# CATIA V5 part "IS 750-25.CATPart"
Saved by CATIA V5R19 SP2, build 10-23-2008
Part number: IS 750-25
Bounding box of the stored display mesh (mm): x -24.865 to 24.865, y -24.997 to 24.997, z 0 to 145
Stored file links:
  C:\Users\Bora\Desktop\3D Katı model\IS serisi\IS 750\IS 750-25.CATPart
  C:\Program Files\Dassault Systemes\B19\intel_a\reffiles\standard\MetricThickPitch.txt
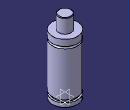
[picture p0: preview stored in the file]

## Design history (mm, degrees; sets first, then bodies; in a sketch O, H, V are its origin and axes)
Body1 (main body)
  Sketch1 on yz-plane, origin (0, 0, 0), H (0, 1, 0), V (0, 0, 1)
    point P1 (25, 104.5)
    point P4 (25, 100.5)
    point P7 (12.5, 144)
    point P9 (12.5, 144)
    point P13 (25, 104.5)
    point P14 (25, 100.5)
    line L1 (25, 104.5) -> (25, 117)
    line L2 (25, 13) -> (25, 100.5)
    line L3 (21.5, 13) -> (21.5, 8)
    arc A1 centre (11.5, 144) radius 1 from (12.5, 144) to (11.5, 145) ccw
    line L4 (12.5, 144) -> (12.5, 117)
    line L5 (25, 0) -> (25, 8)
    arc A2 centre (25, 102.5) radius 2 from (25, 104.5) to (25, 100.5) ccw
    line L6 (11.5, 145) -> (0, 145)
    point P15 (0, 145)
    line L7 (12.5, 117) -> (25, 117)
    line L8 (0, 0) -> (25, 0)
    line L9 (21.5, 8) -> (25, 8)
    line L10 (21.5, 13) -> (25, 13)
    tangency: L6 A1
    coincidence: P15 V, P1 P13, P4 P14, P7 P9
    horizontal: L7 H, L8 H, L9 H, L10 H
  Shaft1: profile Sketch1, axis Sketch1.V, angle 360
  Sketch2 on face of Shaft1 from Sketch1.L8, origin (0, 0, 0), H (1, 0, 0), V (0, -1, 0)
    point P1 (10, 0)
    distance P1 V = 10
  Hole1: placed by Sketch2, at (10, 0, 0) direction (0, 0, 1), diameter 6.647, depth 13, threaded "M8", thread diameter 8, thread depth 13, pitch 1.25
  Sketch3 on face of Shaft1 from Sketch1.L8, origin (0, 0, 0), H (1, 0, 0), V (0, -1, 0)
    point P1 (-10, 0)
    distance P1 V = 10
  Hole2: placed by Sketch3, at (-10, 0, 0) direction (0, 0, 1), diameter 6.647, depth 13, threaded "M8", thread diameter 8, thread depth 13, pitch 1.25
